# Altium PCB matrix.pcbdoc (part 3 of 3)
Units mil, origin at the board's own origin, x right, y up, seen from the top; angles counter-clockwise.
Board outline 9450 x 9250 mil, 2 copper layers (Top Layer, Bottom Layer); 316 components, 228 nets, 906 pads, 1393 vias.
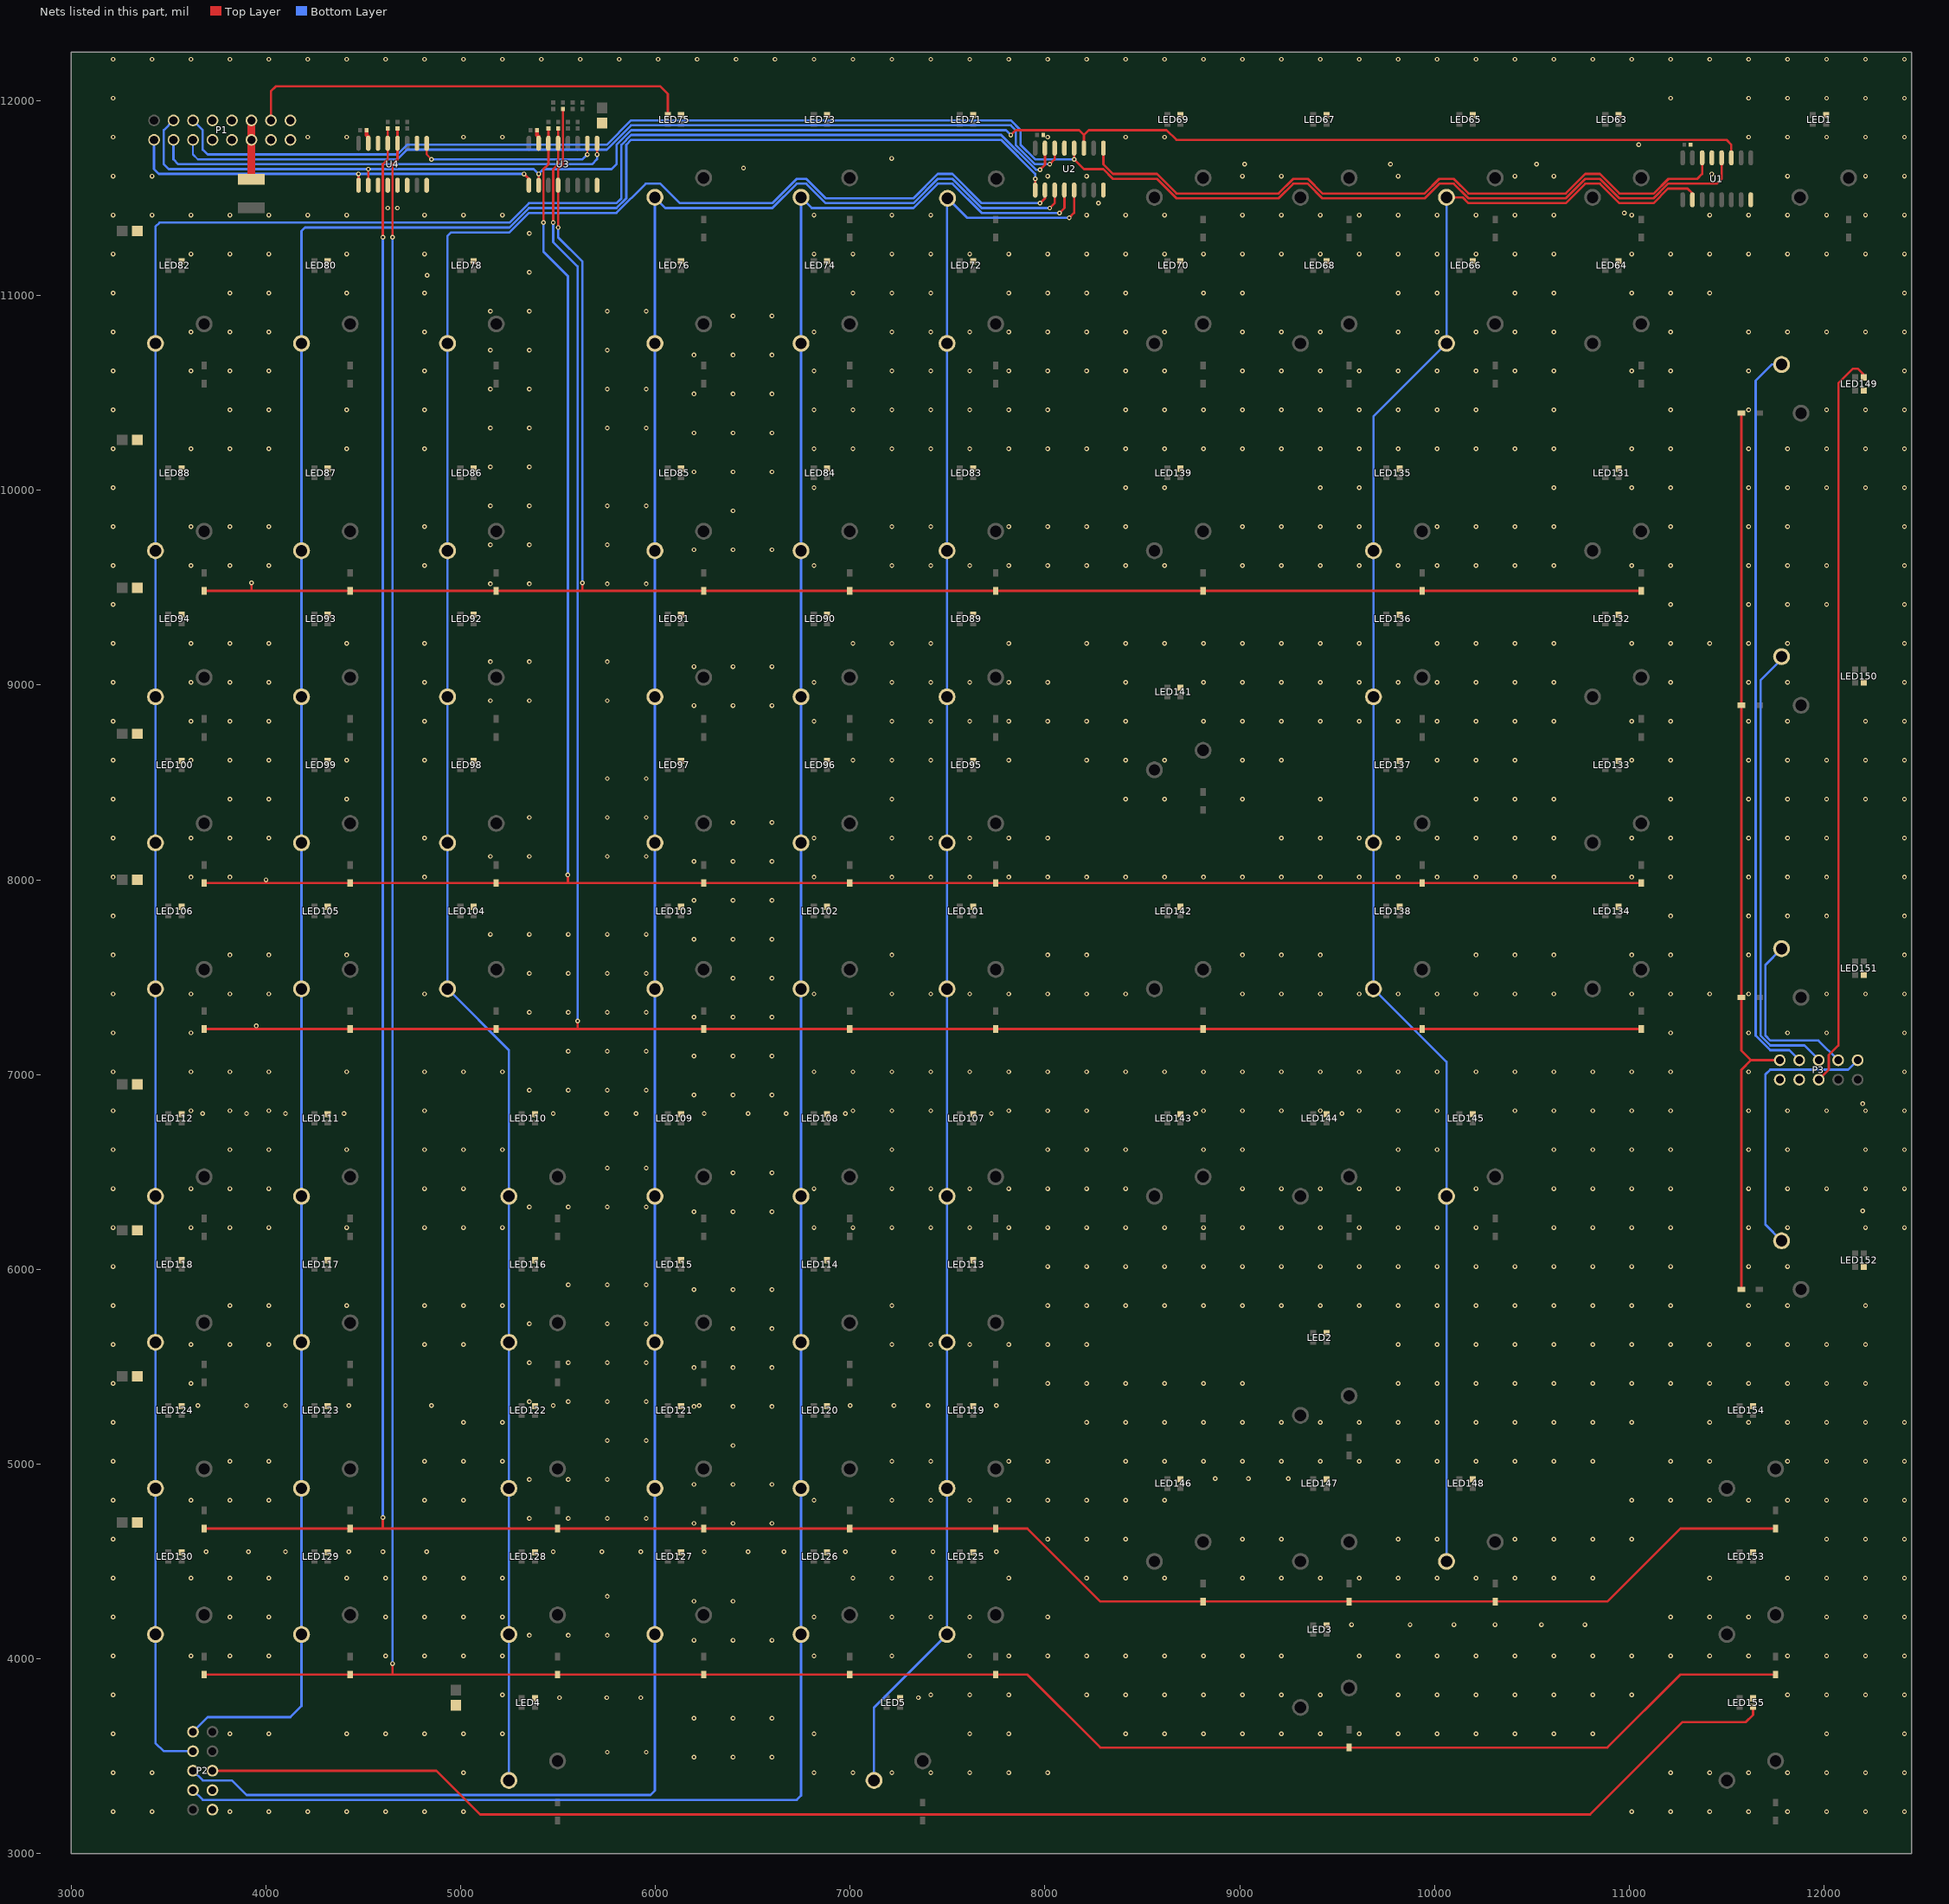
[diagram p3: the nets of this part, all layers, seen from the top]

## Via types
v1: diameter 24.02, hole 12.01, Top Layer to Bottom Layer, 1393 vias

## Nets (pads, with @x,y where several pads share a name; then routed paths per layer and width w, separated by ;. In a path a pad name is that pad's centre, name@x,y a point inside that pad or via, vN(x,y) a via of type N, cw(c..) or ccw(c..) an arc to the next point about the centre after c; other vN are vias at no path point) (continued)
$1N8772: D149.2 D150.2 D151.2 D152.2 P3.10 | length 4688.5
  Top Layer w12: D152.2@11576.75,5896.45 11576.75,7024.23 11626.26,7073.74 ; D149.2@11576.75,10396.45 D150.2@11576.75,8896.45 D151.2@11576.75,7396.45 11576.75,7123.26 11626.26,7073.74 ; P3.10@11773.73,7073.74 11626.26,7073.74
$1N12570: D83.2 D84.2 D85.2 D86.2 D87.2 D88.2 D131.2 D135.2 D139.2 R3.1 U3.4 | length 9958.4
  Top Layer w12: D88.2@3682.29,9483.81 3923.64,9483.81 ; v1(3925,9525) 3925,9485.17 3923.64,9483.81 ; v1(5500,11350) U3.4@5500,11567.3 5500,11650 5525,11675 R3.1@5525,11957.96 ; v1(5625,9525) 5625,9484.81 5624,9483.81 ; D131.2@11062.29,9483.81 D135.2@9937.29,9483.81 D139.2@8812.29,9483.81 D83.2@7747.29,9483.81 D84.2@6997.29,9483.81 D85.2@6247.29,9483.81 5624,9483.81 ; 3923.64,9483.81 D87.2@4432.29,9483.81 D86.2@5182.29,9483.81 5624,9483.81
  Bottom Layer w12: v1(5500,11350) 5500,11300 5625,11175 v1(5625,9525)
$1N12677: D101.2 D102.2 D103.2 D104.2 D105.2 D106.2 D134.2 D138.2 D142.2 R6.1 U3.13 | length 12075.3
  Top Layer w12: D106.2@3682.29,7233.81 3950.92,7233.81 ; v1(3950,7250) 3950,7234.74 3950.92,7233.81 ; v1(5475,11375) 5475,11650 5500,11675 U3.13@5500,11782.7 R6.1@5500,11850 ; v1(5600,7275) 5600,7234.85 5598.96,7233.81 ; D134.2@11062.29,7233.81 D138.2@9937.29,7233.81 D142.2@8812.29,7233.81 D101.2@7747.29,7233.81 D102.2@6997.29,7233.81 D103.2@6247.29,7233.81 5598.96,7233.81 ; 3950.92,7233.81 D105.2@4432.29,7233.81 D104.2@5182.29,7233.81 5598.96,7233.81
  Bottom Layer w12: v1(5475,11375) 5475,11275 5600,11150 v1(5600,7275)
$1N14585: D95.2 D96.2 D97.2 D98.2 D99.2 D100.2 D133.2 D137.2 R5.1 U3.14 | length 11335.1
  Top Layer w12: D100.2@3682.29,7983.81 3994.97,7983.81 ; v1(4000,8000) 4000,7988.85 3994.97,7983.81 ; v1(5425,11375) 5425,11650 5450,11675 U3.14@5450,11782.7 R5.1@5450,11857.96 ; v1(5550,8025) 5550,7985.21 5551.4,7983.81 ; D133.2@11062.29,7983.81 D137.2@9937.29,7983.81 D95.2@7747.29,7983.81 D96.2@6997.29,7983.81 D97.2@6247.29,7983.81 5551.4,7983.81 ; 3994.97,7983.81 D99.2@4432.29,7983.81 D98.2@5182.29,7983.81 5551.4,7983.81
  Bottom Layer w12: v1(5425,11375) 5425,11225 5550,11100 v1(5550,8025)
$1N14611: D119.2 D120.2 D121.2 D122.2 D123.2 D124.2 D146.2 D147.2 D148.2 D154.2 R9.1 U4.13 | length 15580.5
  Top Layer w12: D124.2@3682.29,4668.81 D123.2@4432.29,4668.81 4599.13,4668.81 ; v1(4600,4725) 4600,4669.68 4599.13,4668.81 ; v1(4600,11300) 4600,11675 4625,11700 U4.13@4625,11782.7 R9.1@4625,11857.96 ; D154.2@11752.29,4668.81 11263.01,4668.81 10888.01,4293.81 D148.2@10312.29,4293.81 D147.2@9562.29,4293.81 D146.2@8812.29,4293.81 8285,4293.81 7910,4668.81 D119.2@7747.29,4668.81 D120.2@6997.29,4668.81 D121.2@6247.29,4668.81 D122.2@5497.29,4668.81 4599.13,4668.81
  Bottom Layer w12: v1(4600,4725) v1(4600,11300)
$1N15532: SW65.2 SW66.2 SW135.2 SW136.2 SW137.2 SW138.2 SW145.2 SW148.2 U1.2 | length 8747.7
  Top Layer w12: SW65.2@10062.29,11504.97 10145.03,11504.97 10175,11475 10675,11475 10775,11575 10850,11575 10950,11475 11125,11475 11200,11550 11300,11550 11325,11525 U1.2@11325,11492.3
  Bottom Layer w12: SW148.2@10062.29,4499.97 SW145.2@10062.29,6374.97 10062.29,7064.97 SW138.2@9687.29,7439.97 SW137.2@9687.29,8189.97 SW136.2@9687.29,8939.97 SW135.2@9687.29,9689.97 9687.29,10379.97 SW66.2@10062.29,10754.97 SW65.2@10062.29,11504.97
$1N16554: F1.1 P1.11 P1.12 | length 302
  Top Layer w40: F1.1@3925,11597.97 P1.12@3925,11800 P1.11@3925,11900
$1N17072: P2.4 SW82.2 SW88.2 SW94.2 SW100.2 SW106.2 SW112.2 SW118.2 SW124.2 SW130.2 U2.15 | length 13090.5
  Top Layer w12: v1(7975,11647.01) 8000,11672.01 U2.15@8000,11757.7
  Bottom Layer w12: P2.4@3625,3525 3475,3525 3432.29,3567.71 SW130.2@3432.29,4124.97 SW124.2@3432.29,4874.97 SW118.2@3432.29,5624.97 SW112.2@3432.29,6374.97 SW106.2@3432.29,7439.97 SW100.2@3432.29,8189.97 SW94.2@3432.29,8939.97 SW88.2@3432.29,9689.97 SW82.2@3432.29,10754.97 3432.29,11354.25 3453.04,11375 5250,11375 5350,11475 5800,11475 5825,11500 5825,11775 5875,11825 7775,11825 7952.99,11647.01 v1(7975,11647.01)
$1N17492: U1.14 U2.9 | length 3551.1
  Top Layer w12: U2.9@8300,11757.7 8300,11675 8350,11625 8575,11625 8675,11525 9200,11525 9275,11600 9350,11600 9425,11525 9950,11525 10025,11600 10100,11600 10175,11525 10675,11525 10775,11625 10850,11625 10950,11525 11127.35,11525 11202.35,11600 11350,11600 11375,11625 U1.14@11375,11707.7
$1N19321: LED149.3 P3.5 | length 3806
  Top Layer w12: P3.5@11973.73,6973.74 12024.99,7025 12025,7100 12075,7150 12075,10550 12150,10625 12175,10625 12204.57,10595.43 LED149.3@12204.57,10580.51
$1N19444: P3.8 SW149.2 | length 3806.8
  Bottom Layer w12: SW149.2@11782.91,10646.45 11732.91,10646.45 11650,10563.55 11650,7200 11725,7125 11822.48,7125 P3.8@11873.73,7073.74
$1N19455: P3.6 SW150.2 | length 2343.7
  Bottom Layer w12: SW150.2@11782.91,9146.45 11782.91,9132.92 11675,9025.01 11675,7200 11725,7150 11900,7150 11973.73,7076.27 P3.6@11973.73,7073.74
$1N19459: P3.2 SW152.2 | length 1392.2
  Bottom Layer w12: SW152.2@11782.91,6146.45 11700,6229.36 11700,7000 11725,7025 12125,7025 P3.2@12173.73,7073.74
$1N19463: P3.4 SW151.2 | length 906.8
  Bottom Layer w12: SW151.2@11782.91,7646.45 11700,7563.55 11700,7200 11725,7175 11972.48,7175 P3.4@12073.73,7073.74
$1N19760: LED155.1 P2.5 | length 8258.3
  Top Layer w12: P2.5@3725,3425 4875,3425 5099.52,3200.48 7391.03,3200.48 7391.52,3200 10800,3200 11275,3675 11600,3675 11636.35,3711.35 LED155.1@11636.35,3753.33
$1N21463: D3.2 D125.2 D126.2 D127.2 D128.2 D129.2 D130.2 D153.2 R10.1 U4.12 | length 16330.5
  Top Layer w12: D130.2@3682.29,3918.81 D129.2@4432.29,3918.81 4650.76,3918.81 ; v1(4650,3975) 4650,3919.57 4650.76,3918.81 ; v1(4650,11300) 4650,11675 4675,11700 U4.12@4675,11782.7 R10.1@4675,11857.96 ; D153.2@11752.29,3918.81 11263.02,3918.81 10888.02,3543.81 D3.2@9562.29,3543.81 8285,3543.81 7910,3918.81 D125.2@7747.29,3918.81 D126.2@6997.29,3918.81 D127.2@6247.29,3918.81 D128.2@5497.29,3918.81 4650.76,3918.81
  Bottom Layer w12: v1(4650,3975) v1(4650,11300)
$1N21690: P2.2 SW80.2 SW87.2 SW93.2 SW99.2 SW105.2 SW111.2 SW117.2 SW123.2 SW129.2 U2.1 | length 12464.8
  Top Layer w12: U2.1@7950,11542.3 v1(7950,11600)
  Bottom Layer w12: P2.2@3625,3625 3700,3700 4125,3700 4182.29,3757.29 SW129.2@4182.29,4124.97 SW123.2@4182.29,4874.97 SW117.2@4182.29,5624.97 SW111.2@4182.29,6374.97 SW105.2@4182.29,7439.97 SW99.2@4182.29,8189.97 SW93.2@4182.29,8939.97 SW87.2@4182.29,9689.97 SW80.2@4182.29,10754.97 4182.29,11332.29 4200,11350 5250,11350 5350,11450 5800,11450 5850,11500 5850,11775 5875,11800 7775,11800 7950,11625 v1(7950,11600)
$1N21742: P2.6 SW75.2 SW76.2 SW85.2 SW91.2 SW97.2 SW103.2 SW109.2 SW115.2 SW121.2 SW127.2 U2.3 | length 12950.3
  Top Layer w12: v1(8025,11450) 8050,11475 U2.3@8050,11517.3
  Bottom Layer w12: P2.6@3625,3425 3675,3375 3825,3375 3900,3300 5975,3300 5997.29,3322.29 SW127.2@5997.29,4124.97 SW121.2@5997.29,4874.97 SW115.2@5997.29,5624.97 SW109.2@5997.29,6374.97 SW103.2@5997.29,7439.97 SW97.2@5997.29,8189.97 SW91.2@5997.29,8939.97 SW85.2@5997.29,9689.97 SW76.2@5997.29,10754.97 SW75.2@5997.29,11502.71 ; SW75.2@5997.29,11504.97 SW75.2@5997.29,11502.71 ; v1(8025,11450) 7675,11450 7525,11600 7450,11600 7325,11475 6875,11475 6775,11575 6725,11575 6600,11450 6050,11450 SW75.2@5997.29,11502.71
$1N21793: P2.8 SW73.2 SW74.2 SW84.2 SW90.2 SW96.2 SW102.2 SW108.2 SW114.2 SW120.2 SW126.2 U2.4 | length 12927
  Top Layer w12: v1(8075,11425) 8100,11450 U2.4@8100,11517.3
  Bottom Layer w12: P2.8@3625,3325 3675,3275 6725,3275 6747.29,3297.29 SW126.2@6747.29,4124.97 SW120.2@6747.29,4874.97 SW114.2@6747.29,5624.97 SW108.2@6747.29,6374.97 SW102.2@6747.29,7439.97 SW96.2@6747.29,8189.97 SW90.2@6747.29,8939.97 SW84.2@6747.29,9689.97 SW74.2@6747.29,10754.97 SW73.2@6747.29,11504.97 6802.26,11450 7325,11450 7450,11575 7525,11575 7675,11425 v1(8075,11425)
$1N21809: SW5.2 SW71.2 SW72.2 SW83.2 SW89.2 SW95.2 SW101.2 SW107.2 SW113.2 SW119.2 SW125.2 U2.5 | length 9108.2
  Top Layer w12: v1(8125,11400) 8150,11425 U2.5@8150,11542.3
  Bottom Layer w12: SW5.2@7122.29,3374.97 7122.29,3749.97 SW125.2@7497.29,4124.97 SW119.2@7497.29,4874.97 SW113.2@7497.29,5624.97 SW107.2@7497.29,6374.97 SW101.2@7497.29,7439.97 SW95.2@7497.29,8189.97 SW89.2@7497.29,8939.97 SW83.2@7497.29,9689.97 SW72.2@7497.29,10754.97 SW71.2@7497.29,11502.71 ; SW71.2@7497.29,11504.97 SW71.2@7497.29,11502.71 ; v1(8125,11400) 7600,11400 SW71.2@7497.29,11502.71
$1N22008: SW4.2 SW78.2 SW86.2 SW92.2 SW98.2 SW104.2 SW110.2 SW116.2 SW122.2 SW128.2 U2.2 | length 11542.6
  Top Layer w12: v1(7975,11475) 8000,11500 U2.2@8000,11542.3
  Bottom Layer w12: SW4.2@5247.29,3374.97 SW128.2@5247.29,4124.97 SW122.2@5247.29,4874.97 SW116.2@5247.29,5624.97 SW110.2@5247.29,6374.97 5247.29,7124.97 SW104.2@4932.29,7439.97 SW98.2@4932.29,8189.97 SW92.2@4932.29,8939.97 SW86.2@4932.29,9689.97 SW78.2@4932.29,10754.97 4932.29,11307.29 4950,11325 5250,11325 5350,11425 5800,11425 5950,11575 6025,11575 6125,11475 6600,11475 6725,11600 6775,11600 6875,11500 7325,11500 7450,11625 7525,11625 7675,11475 v1(7975,11475)
$1N28901: U3.10 U4.9 | length 961.1
  Top Layer w10: U4.9@4825,11782.7 4825,11725 v1(4850,11700) ; v1(5650,11725) U3.10@5650,11782.7
  Bottom Layer w12: v1(4850,11700) 5625,11700 v1(5650,11725)
COLL: P1.5 U1.12 U2.12 | length 8677.1
  Top Layer w12: U2.12@8150,11757.7 v1(8150,11700) 8200,11650 8300,11650 8350,11600 8575,11600 8675,11500 9200,11500 9275,11575 9350,11575 9425,11500 9950,11500 10025,11575 10100,11575 10175,11500 10675,11500 10775,11600 10850,11600 10950,11500 11125,11500 11200,11575 11450,11575 11475,11600 U1.12@11475,11707.7
  Bottom Layer w12: P1.5@3625,11900 3675,11850 3675,11750 3700,11725 4675,11725 4725,11775 5750,11775 5875,11900 7825,11900 7875,11850 7875,11775 7950,11700 v1(8150,11700)
COLS: P1.6 U2.14 | length 4777.7
  Top Layer w12: v1(8025,11675) 8050,11700 U2.14@8050,11757.7
  Bottom Layer w10: P1.6@3625,11800 3625,11725 3650,11700
  Bottom Layer w12: 3650,11700 4675,11700 4725,11750 5750,11750 5875,11875 7825,11875 7850,11850 7850,11775 7950,11675 v1(8025,11675)
GND: C1.1 C2.1 C3.2 C4.1 C5.1 C6.1 C7.1 C8.1 C9.1 C10.1 C11.1 C15.1 C16.1 C17.1 C18.1 LED1.2 LED2.2 LED3.2 LED4.2 LED5.2 LED63.2 LED64.2 LED65.2 LED66.2 LED67.2 LED68.2 LED69.2 LED70.2 LED71.2 LED72.2 LED73.2 LED74.2 LED75.2 LED76.2 LED78.2 LED80.2 LED82.2 LED83.2 LED84.2 LED85.2 LED86.2 LED87.2 LED88.2 LED89.2 LED90.2 LED91.2 LED92.2 LED93.2 LED94.2 LED95.2 LED96.2 LED97.2 LED98.2 LED99.2 LED100.2 LED101.2 LED102.2 LED103.2 LED104.2 LED105.2 LED106.2 LED107.2 LED108.2 LED109.2 LED110.2 LED111.2 LED112.2 LED113.2 LED114.2 LED115.2 LED116.2 LED117.2 LED118.2 LED119.2 LED120.2 LED121.2 LED122.2 LED123.2 LED124.2 LED125.2 LED126.2 LED127.2 LED128.2 LED129.2 LED130.2 LED131.2 LED132.2 LED133.2 LED134.2 LED135.2 LED136.2 LED137.2 LED138.2 LED139.2 LED141.2 LED142.2 LED143.2 LED144.2 LED145.2 LED146.2 LED147.2 LED148.2 LED149.2 LED150.2 LED151.2 LED152.2 LED153.2 LED154.2 LED155.2 P1.7 P1.8 P1.9 P1.10 P1.14 P1.15 P1.16 P2.7 P2.9 P3.7 P3.9 U1.8 U1.13 U2.8 U2.13 U3.8 U3.15 U4.3 U4.4 U4.5 U4.6 U4.8 U4.10 U4.14 U4.15 | length 141.6
  Top Layer w20: C15.1@4516.54,11850 4516.54,11825 4525,11816.54 U4.15@4525,11782.7 ; C17.1@5391.54,11850 5391.54,11825 5400,11816.54 U3.15@5400,11782.7
  other v1: 3214.1,3214.1 3414.1,3214.1 3814.1,3214.1 4014.1,3214.1 4214.1,3214.1 4414.1,3214.1 4614.1,3214.1 4814.1,3214.1 5014.1,3214.1 11014.1,3214.1 11214.1,3214.1 11414.1,3214.1 11614.1,3214.1 11814.1,3214.1 12014.1,3214.1 12214.1,3214.1 12414.1,3214.1 3214.1,3414.1 3414.1,3414.1 5014.1,3414.1 6814.1,3414.1 7014.1,3414.1 7214.1,3414.1 7414.1,3414.1 7614.1,3414.1 7814.1,3414.1 8014.1,3414.1 11214.1,3414.1 11414.1,3414.1 11614.1,3414.1 11814.1,3414.1 12014.1,3414.1 12214.1,3414.1 12414.1,3414.1 6198.53,3495.1 6398.53,3495.1 6598.53,3495.1 5752.39,3520.1 5952.39,3520.1 3214.1,3614.1 3814.1,3614.1 4014.1,3614.1 4414.1,3614.1 4614.1,3614.1 4814.1,3614.1 5014.1,3614.1 5214.1,3614.1 6814.1,3614.1 7614.1,3614.1 7814.1,3614.1 8414.1,3614.1 8614.1,3614.1 8814.1,3614.1 9014.1,3614.1 9214.1,3614.1 9414.1,3614.1 9614.1,3614.1 9814.1,3614.1 10014.1,3614.1 10214.1,3614.1 10414.1,3614.1 10614.1,3614.1 10814.1,3614.1 12014.1,3614.1 12414.1,3614.1 6198.53,3695.1 6398.53,3695.1 6598.53,3695.1 5507.53,3799.98 5750,3800 5925,3800 7350,3800 3214.1,3814.1 5214.1,3814.1 7414.1,3814.1 7614.1,3814.1 7814.1,3814.1 8214.1,3814.1 8414.1,3814.1 8614.1,3814.1 8814.1,3814.1 9014.1,3814.1 9214.1,3814.1 9414.1,3814.1 9814.1,3814.1 10014.1,3814.1 10214.1,3814.1 10414.1,3814.1 10614.1,3814.1 10814.1,3814.1 11014.1,3814.1 11814.1,3814.1 12014.1,3814.1 12214.1,3814.1 12414.1,3814.1 3214.1,4014.1 3614.1,4014.1 3814.1,4014.1 4014.1,4014.1 4614.1,4014.1 4814.1,4014.1 5014.1,4014.1 5214.1,4014.1 6814.1,4014.1 7214.1,4014.1 7614.1,4014.1 7814.1,4014.1 8014.1,4014.1 8214.1,4014.1 8414.1,4014.1 8614.1,4014.1 8814.1,4014.1 9014.1,4014.1 9214.1,4014.1 9614.1,4014.1 9814.1,4014.1 10014.1,4014.1 10214.1,4014.1 10414.1,4014.1 10614.1,4014.1 10814.1,4014.1 11014.1,4014.1 11214.1,4014.1 11414.1,4014.1 11614.1,4014.1 11814.1,4014.1 12014.1,4014.1 12214.1,4014.1 12414.1,4014.1 6198.53,4095.1 6398.53,4095.1 6598.53,4095.1 5352.39,4120.1 5552.39,4120.1 5752.39,4120.1 9575,4175 9875,4175 10100,4175 10311.24,4175 10550,4175 10772.85,4175 3214.1,4214.1 3814.1,4214.1 4014.1,4214.1 4614.1,4214.1 4814.1,4214.1 5014.1,4214.1 5214.1,4214.1 6814.1,4214.1 7214.1,4214.1 7414.1,4214.1 7614.1,4214.1 8014.1,4214.1 11214.1,4214.1 11414.1,4214.1 11614.1,4214.1 12014.1,4214.1 12214.1,4214.1 12414.1,4214.1 6198.53,4295.1 6398.53,4295.1 5752.39,4320.1 3214.1,4414.1 3614.1,4414.1 3814.1,4414.1 4014.1,4414.1 4414.1,4414.1 4614.1,4414.1 4814.1,4414.1 5014.1,4414.1 5214.1,4414.1 7014.1,4414.1 7214.1,4414.1 7414.1,4414.1 7814.1,4414.1 8214.1,4414.1 8414.1,4414.1 8614.1,4414.1 9014.1,4414.1 9214.1,4414.1 9414.1,4414.1 9614.1,4414.1 9814.1,4414.1 10014.1,4414.1 10214.1,4414.1 10414.1,4414.1 10614.1,4414.1 10814.1,4414.1 11414.1,4414.1 11814.1,4414.1 12014.1,4414.1 12214.1,4414.1 12414.1,4414.1 3692.89,4550 3910.2,4550 4100,4550 4425,4550 4600,4550 4825,4550 5475,4550 5725,4550 5925,4550 6250,4550 6475,4550 6660.25,4550 6975,4550 7225,4550 7425,4550 7750,4550 3214.1,4614.1 8014.1,4614.1 8214.1,4614.1 8414.1,4614.1 9014.1,4614.1 9214.1,4614.1 9814.1,4614.1 10014.1,4614.1 10414.1,4614.1 10614.1,4614.1 10814.1,4614.1 11014.1,4614.1 12014.1,4614.1 12214.1,4614.1 12414.1,4614.1 6198.53,4695.1 6398.53,4695.1 6598.53,4695.1 5352.39,4720.1 5552.39,4720.1 5752.39,4720.1 5952.39,4720.1 3214.1,4814.1 3614.1,4814.1 3814.1,4814.1 4014.1,4814.1 4814.1,4814.1 5014.1,4814.1 6814.1,4814.1 7214.1,4814.1 7414.1,4814.1 7614.1,4814.1 7814.1,4814.1 8014.1,4814.1 8214.1,4814.1 8414.1,4814.1 8614.1,4814.1 11014.1,4814.1 11214.1,4814.1 11414.1,4814.1 11614.1,4814.1 11814.1,4814.1 12014.1,4814.1 12214.1,4814.1 12414.1,4814.1 6198.53,4895.1 6398.53,4895.1 6598.53,4895.1 5352.39,4920.1 5552.39,4920.1 5752.39,4920.1 8875,4925 9044.65,4925 9250,4925 3214.1,5014.1 3814.1,5014.1 4014.1,5014.1 4814.1,5014.1 5014.1,5014.1 5214.1,5014.1 7214.1,5014.1 7414.1,5014.1 7814.1,5014.1 8014.1,5014.1 8414.1,5014.1 8614.1,5014.1 8814.1,5014.1 9014.1,5014.1 9214.1,5014.1 9414.1,5014.1 9614.1,5014.1 9814.1,5014.1 10014.1,5014.1 10214.1,5014.1 10414.1,5014.1 10614.1,5014.1 10814.1,5014.1 11214.1,5014.1 11414.1,5014.1 11814.1,5014.1 12014.1,5014.1 12214.1,5014.1 12414.1,5014.1 6398.53,5095.1 5752.39,5120.1 5952.39,5120.1 3214.1,5214.1 5014.1,5214.1 5214.1,5214.1 8214.1,5214.1 8414.1,5214.1 8614.1,5214.1 8814.1,5214.1 9014.1,5214.1 9214.1,5214.1 9414.1,5214.1 9614.1,5214.1 9814.1,5214.1 10014.1,5214.1 10214.1,5214.1 10414.1,5214.1 10614.1,5214.1 10814.1,5214.1 11014.1,5214.1 11414.1,5214.1 11614.1,5214.1 11814.1,5214.1 12014.1,5214.1 12214.1,5214.1 12414.1,5214.1 6198.53,5295.1 6398.53,5295.1 6598.53,5295.1 3650,5300 3900,5300 4100,5300 4425,5300 4850,5300 5475,5300 6225,5300 7000,5300 7225,5300 7400,5300 7750,5300 5352.39,5320.1 5552.39,5320.1 5752.39,5320.1 5952.39,5320.1 3214.1,5414.1 3614.1,5414.1 8014.1,5414.1 8214.1,5414.1 8414.1,5414.1 8614.1,5414.1 8814.1,5414.1 9014.1,5414.1 9814.1,5414.1 10014.1,5414.1 10214.1,5414.1 10414.1,5414.1 10614.1,5414.1 10814.1,5414.1 11014.1,5414.1 11214.1,5414.1 11414.1,5414.1 11614.1,5414.1 11814.1,5414.1 12014.1,5414.1 12214.1,5414.1 6198.53,5495.1 6398.53,5495.1 6598.53,5495.1 5352.39,5520.1 5552.39,5520.1 5752.39,5520.1 5952.39,5520.1 3214.1,5614.1 3614.1,5614.1 3814.1,5614.1 4014.1,5614.1 4814.1,5614.1 5014.1,5614.1 7214.1,5614.1 7414.1,5614.1 7614.1,5614.1 7814.1,5614.1 8014.1,5614.1 8214.1,5614.1 9814.1,5614.1 10014.1,5614.1 10214.1,5614.1 10414.1,5614.1 10614.1,5614.1 10814.1,5614.1 11014.1,5614.1 11214.1,5614.1 11414.1,5614.1 11614.1,5614.1 11814.1,5614.1 12014.1,5614.1 12214.1,5614.1 6398.53,5695.1 6598.53,5695.1 5352.39,5720.1 5752.39,5720.1 5952.39,5720.1 3214.1,5814.1 3814.1,5814.1 4014.1,5814.1 4414.1,5814.1 4814.1,5814.1 5014.1,5814.1 5214.1,5814.1 7214.1,5814.1 8014.1,5814.1 8214.1,5814.1 8414.1,5814.1 8614.1,5814.1 8814.1,5814.1 9014.1,5814.1 9214.1,5814.1 9414.1,5814.1 9614.1,5814.1 9814.1,5814.1 10014.1,5814.1 10214.1,5814.1 10414.1,5814.1 10614.1,5814.1 10814.1,5814.1 11014.1,5814.1 11214.1,5814.1 11614.1,5814.1 11814.1,5814.1 12214.1,5814.1 6198.53,5895.1 6398.53,5895.1 6598.53,5895.1 5552.39,5920.1 5752.39,5920.1 5952.39,5920.1 3214.1,6014.1 8014.1,6014.1 8214.1,6014.1 8414.1,6014.1 8614.1,6014.1 8814.1,6014.1 9014.1,6014.1 9214.1,6014.1 9414.1,6014.1 9614.1,6014.1 9814.1,6014.1 10014.1,6014.1 10214.1,6014.1 10414.1,6014.1 10614.1,6014.1 10814.1,6014.1 11014.1,6014.1 11214.1,6014.1 11614.1,6014.1 11814.1,6014.1 3214.1,6214.1 3614.1,6214.1 3814.1,6214.1 4014.1,6214.1 4414.1,6214.1 4814.1,6214.1 5014.1,6214.1 5214.1,6214.1 6814.1,6214.1 7014.1,6214.1 7214.1,6214.1 7414.1,6214.1 7614.1,6214.1 7814.1,6214.1 8014.1,6214.1 8214.1,6214.1 8414.1,6214.1 8614.1,6214.1 8814.1,6214.1 9014.1,6214.1 9214.1,6214.1 9414.1,6214.1 9614.1,6214.1 9814.1,6214.1 10014.1,6214.1 10214.1,6214.1 10614.1,6214.1 10814.1,6214.1 11014.1,6214.1 11214.1,6214.1 11614.1,6214.1 11814.1,6214.1 12214.1,6214.1 12414.1,6214.1 6198.53,6295.1 6398.53,6295.1 6598.53,6295.1 12200,6300 5352.39,6320.1 5552.39,6320.1 5752.39,6320.1 5952.39,6320.1 3214.1,6414.1 3614.1,6414.1 3814.1,6414.1 4014.1,6414.1 4814.1,6414.1 5014.1,6414.1 6814.1,6414.1 7214.1,6414.1 7414.1,6414.1 7614.1,6414.1 7814.1,6414.1 8014.1,6414.1 8214.1,6414.1 8414.1,6414.1 9014.1,6414.1 9214.1,6414.1 9414.1,6414.1 9614.1,6414.1 9814.1,6414.1 10214.1,6414.1 10614.1,6414.1 10814.1,6414.1 11014.1,6414.1 11214.1,6414.1 11614.1,6414.1 11814.1,6414.1 12014.1,6414.1 12214.1,6414.1 12414.1,6414.1 6398.53,6495.1 6598.53,6495.1 5752.39,6520.1 5952.39,6520.1 3214.1,6614.1 3814.1,6614.1 4014.1,6614.1 4414.1,6614.1 4814.1,6614.1 5014.1,6614.1 5214.1,6614.1 7214.1,6614.1 8014.1,6614.1 8214.1,6614.1 8414.1,6614.1 8814.1,6614.1 9014.1,6614.1 9814.1,6614.1 10014.1,6614.1 10614.1,6614.1 10814.1,6614.1 11014.1,6614.1 11214.1,6614.1 11614.1,6614.1 11814.1,6614.1 12214.1,6614.1 12414.1,6614.1 3675,6800 3900,6800 4100,6800 4400,6800 5475,6800 5750,6800 5900,6800 6250,6800 6475,6800 6671.2,6800 6975,6800 7725,6800 8775,6800 9525,6800 3214.1,6814.1 3614.1,6814.1 3814.1,6814.1 4014.1,6814.1 4814.1,6814.1 7014.1,6814.1 7214.1,6814.1 7414.1,6814.1 7814.1,6814.1 8014.1,6814.1 8214.1,6814.1 8814.1,6814.1 9014.1,6814.1 9214.1,6814.1 9414.1,6814.1 9614.1,6814.1 9814.1,6814.1 10014.1,6814.1 10414.1,6814.1 10614.1,6814.1 10814.1,6814.1 11014.1,6814.1 11214.1,6814.1 11614.1,6814.1 11814.1,6814.1 12014.1,6814.1 12214.1,6814.1 12414.1,6814.1 12200,6850 6198.53,6895.1 6398.53,6895.1 6598.53,6895.1 5352.39,6920.1 5552.39,6920.1 5752.39,6920.1 5952.39,6920.1 3214.1,7014.1 3614.1,7014.1 3814.1,7014.1 4014.1,7014.1 4414.1,7014.1 4814.1,7014.1 5014.1,7014.1 5214.1,7014.1 6814.1,7014.1 7014.1,7014.1 7214.1,7014.1 7414.1,7014.1 7614.1,7014.1 7814.1,7014.1 8014.1,7014.1 8214.1,7014.1 8414.1,7014.1 8614.1,7014.1 8814.1,7014.1 9014.1,7014.1 9214.1,7014.1 9414.1,7014.1 9614.1,7014.1 9814.1,7014.1 10014.1,7014.1 10214.1,7014.1 10414.1,7014.1 10614.1,7014.1 10814.1,7014.1 11014.1,7014.1 11214.1,7014.1 11614.1,7014.1 12414.1,7014.1 6198.53,7095.1 6398.53,7095.1 6598.53,7095.1 5552.39,7120.1 5752.39,7120.1 5952.39,7120.1 3214.1,7214.1 3614.1,7214.1 11214.1,7214.1 11614.1,7214.1 11814.1,7214.1 12014.1,7214.1 12414.1,7214.1 6198.53,7295.1 6398.53,7295.1 6598.53,7295.1 5352.39,7320.1 5552.39,7320.1 5752.39,7320.1 5952.39,7320.1 3214.1,7414.1 3614.1,7414.1 3814.1,7414.1 4014.1,7414.1 4814.1,7414.1 6814.1,7414.1 7214.1,7414.1 7414.1,7414.1 7614.1,7414.1 7814.1,7414.1 8014.1,7414.1 8214.1,7414.1 8414.1,7414.1 9014.1,7414.1 9214.1,7414.1 9414.1,7414.1 9614.1,7414.1 9814.1,7414.1 10014.1,7414.1 10214.1,7414.1 10414.1,7414.1 10614.1,7414.1 11014.1,7414.1 11214.1,7414.1 11414.1,7414.1 11614.1,7414.1 12014.1,7414.1 12214.1,7414.1 12414.1,7414.1 6398.53,7495.1 6598.53,7495.1 5352.39,7520.1 5552.39,7520.1 5752.39,7520.1 5952.39,7520.1 3214.1,7614.1 3814.1,7614.1 4014.1,7614.1 4414.1,7614.1 7214.1,7614.1 8014.1,7614.1 8214.1,7614.1 9014.1,7614.1 9214.1,7614.1 9414.1,7614.1 10214.1,7614.1 10414.1,7614.1 10614.1,7614.1 11014.1,7614.1 11214.1,7614.1 11614.1,7614.1 12414.1,7614.1 6198.53,7695.1 6398.53,7695.1 6598.53,7695.1 5152.39,7720.1 5352.39,7720.1 5552.39,7720.1 5752.39,7720.1 5952.39,7720.1 3214.1,7814.1 11214.1,7814.1 11614.1,7814.1 11814.1,7814.1 12014.1,7814.1 12414.1,7814.1 6198.53,7895.1 6398.53,7895.1 6598.53,7895.1 3214.1,8014.1 3614.1,8014.1 3814.1,8014.1 4814.1,8014.1 6814.1,8014.1 7214.1,8014.1 7414.1,8014.1 7614.1,8014.1 7814.1,8014.1 8014.1,8014.1 8214.1,8014.1 8414.1,8014.1 8614.1,8014.1 8814.1,8014.1 9014.1,8014.1 9214.1,8014.1 9414.1,8014.1 9614.1,8014.1 9814.1,8014.1 10014.1,8014.1 10214.1,8014.1 10414.1,8014.1 10614.1,8014.1 11014.1,8014.1 11214.1,8014.1 11614.1,8014.1 11814.1,8014.1 12014.1,8014.1 12414.1,8014.1 6198.53,8095.1 6398.53,8095.1 6598.53,8095.1 5152.39,8120.1 5352.39,8120.1 5752.39,8120.1 5952.39,8120.1 3214.1,8214.1 3614.1,8214.1 3814.1,8214.1 4014.1,8214.1 4814.1,8214.1 6814.1,8214.1 7214.1,8214.1 7414.1,8214.1 7614.1,8214.1 7814.1,8214.1 8014.1,8214.1 9214.1,8214.1 9414.1,8214.1 9614.1,8214.1 9814.1,8214.1 10014.1,8214.1 10214.1,8214.1 10414.1,8214.1 10614.1,8214.1 11014.1,8214.1 11214.1,8214.1 11614.1,8214.1 11814.1,8214.1 12014.1,8214.1 12414.1,8214.1 6398.53,8295.1 6598.53,8295.1 5352.39,8320.1 5752.39,8320.1 5952.39,8320.1 3214.1,8414.1 3814.1,8414.1 4014.1,8414.1 4414.1,8414.1 7214.1,8414.1 8414.1,8414.1 8614.1,8414.1 9014.1,8414.1 9414.1,8414.1 10214.1,8414.1 10414.1,8414.1 10614.1,8414.1 11214.1,8414.1 11614.1,8414.1 11814.1,8414.1 12014.1,8414.1 12214.1,8414.1 12414.1,8414.1 5752.39,8520.1 5952.39,8520.1 3214.1,8614.1 3614.1,8614.1 3814.1,8614.1 4014.1,8614.1 4414.1,8614.1 4814.1,8614.1 7014.1,8614.1 7214.1,8614.1 7414.1,8614.1 7814.1,8614.1 8214.1,8614.1 8414.1,8614.1 8614.1,8614.1 9014.1,8614.1 9214.1,8614.1 10014.1,8614.1 10214.1,8614.1 10414.1,8614.1 11014.1,8614.1 11214.1,8614.1 11614.1,8614.1 11814.1,8614.1 12014.1,8614.1 12214.1,8614.1 12414.1,8614.1 3214.1,8814.1 3614.1,8814.1 3814.1,8814.1 4014.1,8814.1 4814.1,8814.1 6814.1,8814.1 7214.1,8814.1 7414.1,8814.1 7614.1,8814.1 7814.1,8814.1 8014.1,8814.1 8214.1,8814.1 8414.1,8814.1 8814.1,8814.1 9014.1,8814.1 9214.1,8814.1 9414.1,8814.1 9614.1,8814.1 9814.1,8814.1 10014.1,8814.1 10214.1,8814.1 10414.1,8814.1 10614.1,8814.1 11014.1,8814.1 11214.1,8814.1 11614.1,8814.1 11814.1,8814.1 12214.1,8814.1 12414.1,8814.1 6198.53,8895.1 6398.53,8895.1 6598.53,8895.1 5152.39,8920.1 5352.39,8920.1 5752.39,8920.1 3214.1,9014.1 3614.1,9014.1 3814.1,9014.1 4014.1,9014.1 4814.1,9014.1 6814.1,9014.1 7214.1,9014.1 7414.1,9014.1 7614.1,9014.1 7814.1,9014.1 8014.1,9014.1 8414.1,9014.1 8814.1,9014.1 9014.1,9014.1 9214.1,9014.1 9414.1,9014.1 9614.1,9014.1 9814.1,9014.1 10014.1,9014.1 10214.1,9014.1 10414.1,9014.1 10614.1,9014.1 11214.1,9014.1 11614.1,9014.1 11814.1,9014.1 12414.1,9014.1 6198.53,9095.1 6398.53,9095.1 6598.53,9095.1 5152.39,9120.1 5352.39,9120.1 5752.39,9120.1 3214.1,9214.1 3614.1,9214.1 3814.1,9214.1 4014.1,9214.1 4414.1,9214.1 4814.1,9214.1 7014.1,9214.1 7214.1,9214.1 7414.1,9214.1 7814.1,9214.1 8214.1,9214.1 8414.1,9214.1 8614.1,9214.1 8814.1,9214.1 9014.1,9214.1 9214.1,9214.1 9414.1,9214.1 9614.1,9214.1 10014.1,9214.1 10214.1,9214.1 10414.1,9214.1 10614.1,9214.1 11014.1,9214.1 11214.1,9214.1 11414.1,9214.1 11614.1,9214.1 11814.1,9214.1 12414.1,9214.1 3214.1,9414.1 11214.1,9414.1 11614.1,9414.1 11814.1,9414.1 12014.1,9414.1 12414.1,9414.1 5152.39,9520.1 5352.39,9520.1 5752.39,9520.1 5952.39,9520.1 3214.1,9614.1 3614.1,9614.1 3814.1,9614.1 4014.1,9614.1 4814.1,9614.1 6814.1,9614.1 7214.1,9614.1 7414.1,9614.1 7614.1,9614.1 7814.1,9614.1 8014.1,9614.1 8214.1,9614.1 8414.1,9614.1 8614.1,9614.1 9014.1,9614.1 9214.1,9614.1 9414.1,9614.1 9614.1,9614.1 9814.1,9614.1 10014.1,9614.1 10214.1,9614.1 10414.1,9614.1 10614.1,9614.1 11014.1,9614.1 11214.1,9614.1 11614.1,9614.1 11814.1,9614.1 12014.1,9614.1 12414.1,9614.1 6198.53,9695.1 6398.53,9695.1 6598.53,9695.1 5152.39,9720.1 5352.39,9720.1 5752.39,9720.1 3214.1,9814.1 3614.1,9814.1 3814.1,9814.1 4014.1,9814.1 4814.1,9814.1 7214.1,9814.1 7414.1,9814.1 7814.1,9814.1 8014.1,9814.1 8214.1,9814.1 8414.1,9814.1 9014.1,9814.1 9214.1,9814.1 9414.1,9814.1 9614.1,9814.1 10014.1,9814.1 10214.1,9814.1 10414.1,9814.1 10614.1,9814.1 11214.1,9814.1 11614.1,9814.1 11814.1,9814.1 12414.1,9814.1 6398.53,9895.1 5152.39,9920.1 5352.39,9920.1 5752.39,9920.1 5952.39,9920.1 3214.1,10014.1 6814.1,10014.1 8414.1,10014.1 8614.1,10014.1 9414.1,10014.1 9614.1,10014.1 10614.1,10014.1 11014.1,10014.1 11214.1,10014.1 11614.1,10014.1 11814.1,10014.1 12014.1,10014.1 12214.1,10014.1 12414.1,10014.1 6198.53,10095.1 6398.53,10095.1 6598.53,10095.1 5152.39,10120.1 5352.39,10120.1 3214.1,10214.1 3614.1,10214.1 3814.1,10214.1 4014.1,10214.1 4414.1,10214.1 4814.1,10214.1 6814.1,10214.1 7014.1,10214.1 7214.1,10214.1 7414.1,10214.1 7614.1,10214.1 7814.1,10214.1 8014.1,10214.1 8214.1,10214.1 8414.1,10214.1 8614.1,10214.1 8814.1,10214.1 9014.1,10214.1 9214.1,10214.1 9414.1,10214.1 9614.1,10214.1 9814.1,10214.1 10014.1,10214.1 10214.1,10214.1 10414.1,10214.1 10614.1,10214.1 11014.1,10214.1 11214.1,10214.1 11614.1,10214.1 11814.1,10214.1 12014.1,10214.1 12214.1,10214.1 12414.1,10214.1 6198.53,10295.1 6398.53,10295.1 6598.53,10295.1 5152.39,10320.1 5352.39,10320.1 5752.39,10320.1 5952.39,10320.1 3214.1,10414.1 3814.1,10414.1 4014.1,10414.1 4414.1,10414.1 4814.1,10414.1 6814.1,10414.1 7014.1,10414.1 7214.1,10414.1 7414.1,10414.1 7614.1,10414.1 7814.1,10414.1 8014.1,10414.1 8414.1,10414.1 8614.1,10414.1 8814.1,10414.1 9014.1,10414.1 9214.1,10414.1 9414.1,10414.1 9614.1,10414.1 9814.1,10414.1 10014.1,10414.1 10214.1,10414.1 10614.1,10414.1 11214.1,10414.1 11614.1,10414.1 12014.1,10414.1 12214.1,10414.1 12414.1,10414.1 6198.53,10495.1 6398.53,10495.1 6598.53,10495.1 5152.39,10520.1 5352.39,10520.1 5752.39,10520.1 5952.39,10520.1 3214.1,10614.1 3614.1,10614.1 3814.1,10614.1 4014.1,10614.1 4814.1,10614.1 6814.1,10614.1 7214.1,10614.1 7414.1,10614.1 7614.1,10614.1 7814.1,10614.1 8014.1,10614.1 8214.1,10614.1 8414.1,10614.1 8614.1,10614.1 9014.1,10614.1 9214.1,10614.1 9414.1,10614.1 9614.1,10614.1 9814.1,10614.1 10014.1,10614.1 10214.1,10614.1 10414.1,10614.1 10614.1,10614.1 11014.1,10614.1 11214.1,10614.1 11614.1,10614.1 12414.1,10614.1 6198.53,10695.1 6398.53,10695.1 6598.53,10695.1 5152.39,10720.1 5352.39,10720.1 5752.39,10720.1 3214.1,10814.1 3614.1,10814.1 3814.1,10814.1 4014.1,10814.1 4814.1,10814.1 6814.1,10814.1 7214.1,10814.1 7414.1,10814.1 7614.1,10814.1 7814.1,10814.1 8014.1,10814.1 8214.1,10814.1 8414.1,10814.1 8614.1,10814.1 9014.1,10814.1 9214.1,10814.1 9414.1,10814.1 9814.1,10814.1 10014.1,10814.1 10214.1,10814.1 10414.1,10814.1 10614.1,10814.1 11214.1,10814.1 11614.1,10814.1 11814.1,10814.1 12014.1,10814.1 12214.1,10814.1 12414.1,10814.1 6398.53,10895.1 6598.53,10895.1 5152.39,10920.1 5352.39,10920.1 5752.39,10920.1 5952.39,10920.1 3214.1,11014.1 3814.1,11014.1 4014.1,11014.1 4414.1,11014.1 4814.1,11014.1 7014.1,11014.1 7214.1,11014.1 7414.1,11014.1 7814.1,11014.1 8014.1,11014.1 8214.1,11014.1 8414.1,11014.1 8814.1,11014.1 9014.1,11014.1 9814.1,11014.1 10014.1,11014.1 10414.1,11014.1 10614.1,11014.1 11014.1,11014.1 11214.1,11014.1 11414.1,11014.1 12414.1,11014.1 4827.3,11105 5352.39,11120.1 3214.1,11214.1 3614.1,11214.1 3814.1,11214.1 4014.1,11214.1 4414.1,11214.1 4814.1,11214.1 6814.1,11214.1 7014.1,11214.1 7214.1,11214.1 7414.1,11214.1 7614.1,11214.1 7814.1,11214.1 8014.1,11214.1 8214.1,11214.1 8414.1,11214.1 8614.1,11214.1 8814.1,11214.1 9014.1,11214.1 9214.1,11214.1 9414.1,11214.1 9614.1,11214.1 9814.1,11214.1 10014.1,11214.1 10214.1,11214.1 10414.1,11214.1 10614.1,11214.1 11014.1,11214.1 11214.1,11214.1 11414.1,11214.1 11614.1,11214.1 11814.1,11214.1 12014.1,11214.1 12214.1,11214.1 12414.1,11214.1 5352.39,11320.1 3214.1,11414.1 3414.1,11414.1 3614.1,11414.1 3814.1,11414.1 4014.1,11414.1 4214.1,11414.1 4414.1,11414.1 4814.1,11414.1 5014.1,11414.1 5214.1,11414.1 6814.1,11414.1 7214.1,11414.1 7414.1,11414.1 8214.1,11414.1 8414.1,11414.1 8614.1,11414.1 9014.1,11414.1 9214.1,11414.1 9414.1,11414.1 9614.1,11414.1 9814.1,11414.1 10014.1,11414.1 10214.1,11414.1 10414.1,11414.1 10614.1,11414.1 11014.1,11414.1 11414.1,11414.1 11614.1,11414.1 11814.1,11414.1 12014.1,11414.1 12214.1,11414.1 12414.1,11414.1 10975,11425 4625,11450 4675,11450 8275,11475 3214.1,11614.1 3414.1,11614.1 8014.1,11614.1 8214.1,11614.1 9014.1,11614.1 9214.1,11614.1 9814.1,11614.1 10414.1,11614.1 10614.1,11614.1 11814.1,11614.1 12214.1,11614.1 12414.1,11614.1 11425,11625 6452.3,11655 9025,11675 9775,11675 10525,11675 7212.92,11704.97 11050,11775 3214.1,11814.1 4214.1,11814.1 4414.1,11814.1 5014.1,11814.1 5214.1,11814.1 8014.1,11814.1 8414.1,11814.1 8614.1,11814.1 11614.1,11814.1 11814.1,11814.1 12014.1,11814.1 12214.1,11814.1 12414.1,11814.1 3214.1,12014.1 11214.1,12014.1 11614.1,12014.1 11814.1,12014.1 12014.1,12014.1 12214.1,12014.1 12414.1,12014.1 3214.1,12214.1 3414.1,12214.1 3614.1,12214.1 3814.1,12214.1 4014.1,12214.1 4214.1,12214.1 4414.1,12214.1 4614.1,12214.1 4814.1,12214.1 5014.1,12214.1 5214.1,12214.1 5414.1,12214.1 5614.1,12214.1 5814.1,12214.1 6014.1,12214.1 6214.1,12214.1 6414.1,12214.1 6614.1,12214.1 6814.1,12214.1 7014.1,12214.1 7214.1,12214.1 7414.1,12214.1 7614.1,12214.1 7814.1,12214.1 8014.1,12214.1 8214.1,12214.1 8414.1,12214.1 8614.1,12214.1 8814.1,12214.1 9014.1,12214.1 9214.1,12214.1 9414.1,12214.1 9614.1,12214.1 9814.1,12214.1 10014.1,12214.1 10214.1,12214.1 10414.1,12214.1 10614.1,12214.1 10814.1,12214.1 11014.1,12214.1 11214.1,12214.1 11414.1,12214.1 11614.1,12214.1 11814.1,12214.1 12014.1,12214.1 12214.1,12214.1 12414.1,12214.1
LED: LED75.3 P1.13 | length 2324.6
  Top Layer w12: P1.13@4025,11900 4025,12050 4050,12075 6025,12075 6063.24,12036.76 LED75.3@6063.24,11926.64
ROWL: P1.2 U3.1 U4.1 | length 2186.1
  Top Layer w12: U4.1@4475,11567.3 v1(4475,11625) ; v1(5325,11625) 5350,11600 U3.1@5350,11567.3
  Bottom Layer w12: P1.2@3425,11800 3425,11650 3450,11625 v1(4475,11625) v1(5325,11625)
ROWS: P1.4 U3.9 | length 2378.4
  Top Layer w12: v1(5700,11725) U3.9@5700,11782.7
  Bottom Layer w12: P1.4@3525,11800 3525,11700 3550,11675 5675,11675 5700,11700 v1(5700,11725)
SCK: P1.3 U1.11 U2.11 U3.2 U4.2 | length 8815.7
  Top Layer w12: U4.2@4525,11567.3 v1(4525,11650) ; U3.2@5400,11567.3 v1(5400,11625) ; v1(7825,11825) 7850,11850 8175,11850 8200,11825 ; U2.11@8200,11757.7 8200,11825 ; U1.11@11525,11707.7 11525,11775 11500,11800 8675,11800 8625,11850 8225,11850 8200,11825
  Bottom Layer w12: P1.3@3525,11900 3475,11850 3475,11675 3500,11650 v1(4525,11650) 5375,11650 v1(5400,11625) 5425,11650 5775,11650 5800,11675 5800,11775 5875,11850 7800,11850 v1(7825,11825)
pads on no net: U1.3 U1.4 U1.5 U1.6 U1.7 U1.9 U3.7 U4.7

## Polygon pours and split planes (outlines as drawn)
GND on Top Layer (solid, remove dead copper, pour order 0): 3000,12250 12450,12250 12450,3000 3000,3000
GND on Bottom Layer (solid, remove dead copper, pour order 2): 3000,12250 12450,12250 12450,3000 3000,3000

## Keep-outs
Board Outline Layer:
  circle w1: c11982.9,6646.5 r50
  region: 12032.9,6646.5 cw(c11982.9,6646.5) 11932.9,6646.5 cw(c11982.9,6646.5)
  circle w1: c11982.9,9796.5 r50
  region: 12032.9,9796.5 cw(c11982.9,9796.5) 11932.9,9796.5 cw(c11982.9,9796.5)
  circle w1: c11982.9,8296.5 r50
  region: 12032.9,8296.5 cw(c11982.9,8296.5) 11932.9,8296.5 cw(c11982.9,8296.5)
  circle w1: c10377.3,8905 r50
  region: 10427.3,8905 cw(c10377.3,8905) 10327.3,8905 cw(c10377.3,8905)
  circle w1: c6077.3,3605 r50
  region: 6127.3,3605 cw(c6077.3,3605) 6027.3,3605 cw(c6077.3,3605)
  circle w1: c8777.3,3905 r50
  region: 8827.3,3905 cw(c8777.3,3905) 8727.3,3905 cw(c8777.3,3905)
  circle w1: c8777.3,5905 r50
  region: 8827.3,5905 cw(c8777.3,5905) 8727.3,5905 cw(c8777.3,5905)
  circle w1: c10977.3,5705 r50
  region: 11027.3,5705 cw(c10977.3,5705) 10927.3,5705 cw(c10977.3,5705)
  circle w1: c10377.3,3905 r50
  region: 10427.3,3905 cw(c10377.3,3905) 10327.3,3905 cw(c10377.3,3905)
  circle w1: c5377.3,7105 r50
  region: 5427.3,7105 cw(c5377.3,7105) 5327.3,7105 cw(c5377.3,7105)
  circle w1: c5377.3,10405 r50
  region: 5427.3,10405 cw(c5377.3,10405) 5327.3,10405 cw(c5377.3,10405)
  circle w1: c8127.3,10405 r50
  region: 8177.3,10405 cw(c8127.3,10405) 8077.3,10405 cw(c8127.3,10405)
  circle w1: c8127.3,7105 r50
  region: 8177.3,7105 cw(c8127.3,7105) 8077.3,7105 cw(c8127.3,7105)
  circle w1: c10977.3,7105 r50
  region: 11027.3,7105 cw(c10977.3,7105) 10927.3,7105 cw(c10977.3,7105)
  circle w1: c10977.3,10405 r50
  region: 11027.3,10405 cw(c10977.3,10405) 10927.3,10405 cw(c10977.3,10405)
  circle w1: c4177.3,3605 r50
  region: 4227.3,3605 cw(c4177.3,3605) 4127.3,3605 cw(c4177.3,3605)
  circle w1: c3577.3,7105 r50
  region: 3627.3,7105 cw(c3577.3,7105) 3527.3,7105 cw(c3577.3,7105)
  circle w1: c8127.3,12105 r50
  region: 8177.3,12105 cw(c8127.3,12105) 8077.3,12105 cw(c8127.3,12105)
  circle w1: c11427.3,12005 r50
  region: 11477.3,12005 cw(c11427.3,12005) 11377.3,12005 cw(c11427.3,12005)
  circle w1: c3577.3,10405 r50
  region: 3627.3,10405 cw(c3577.3,10405) 3527.3,10405 cw(c3577.3,10405)
  circle w1: c5077.3,11905 r50
  region: 5127.3,11905 cw(c5077.3,11905) 5027.3,11905 cw(c5077.3,11905)
  region: 11550,11050 12350,11050 12350,11025 11550,11025
  region: 11425,10925 11450,10925 11450,9275 11425,9275
  region: 11550,5575 12350,5575 12350,5550 11550,5550
  region: 11425,9125 11450,9125 11450,7475 11425,7475
  region: 11425,7325 11450,7325 11450,5675 11425,5675
  lines w1: 11425,5675 11450,5675 11450,7325 11425,7325 11425,5675 ; 11425,7475 11450,7475 11450,9125 11425,9125 11425,7475 ; 11425,9275 11450,9275 11450,10925 11425,10925 11425,9275 ; 11550,5550 12350,5550 12350,5575 11550,5575 11550,5550 ; 11550,11025 12350,11025 12350,11050 11550,11050 11550,11025
  lines w10: 3000,3000 12450,3000 12450,12250 3000,12250 3000,3000

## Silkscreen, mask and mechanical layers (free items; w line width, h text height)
Top Silkscreen Layer:
  text "v0.2" at 3075,12050 h120
Mechanical Layer:
  circle w1: c11982.9,6646.5 r50
  circle w1: c11982.9,9796.5 r50
  circle w1: c11982.9,8296.5 r50
  circle w1: c10377.3,8905 r50
  circle w1: c6077.3,3605 r50
  circle w1: c8777.3,3905 r50
  circle w1: c8777.3,5905 r50
  circle w1: c10977.3,5705 r50
  circle w1: c10377.3,3905 r50
  circle w1: c5377.3,7105 r50
  circle w1: c5377.3,10405 r50
  circle w1: c8127.3,10405 r50
  circle w1: c8127.3,7105 r50
  circle w1: c10977.3,7105 r50
  circle w1: c10977.3,10405 r50
  circle w1: c4177.3,3605 r50
  circle w1: c3577.3,7105 r50
  circle w1: c8127.3,12105 r50
  circle w1: c11427.3,12005 r50
  circle w1: c3577.3,10405 r50
  circle w1: c5077.3,11905 r50
  lines w1: 11425,5675 11450,5675 11450,7325 11425,7325 11425,5675 ; 11425,7475 11450,7475 11450,9125 11425,9125 11425,7475 ; 11425,9275 11450,9275 11450,10925 11425,10925 11425,9275 ; 11550,5550 12350,5550 12350,5575 11550,5575 11550,5550 ; 11550,11025 12350,11025 12350,11050 11550,11050 11550,11025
